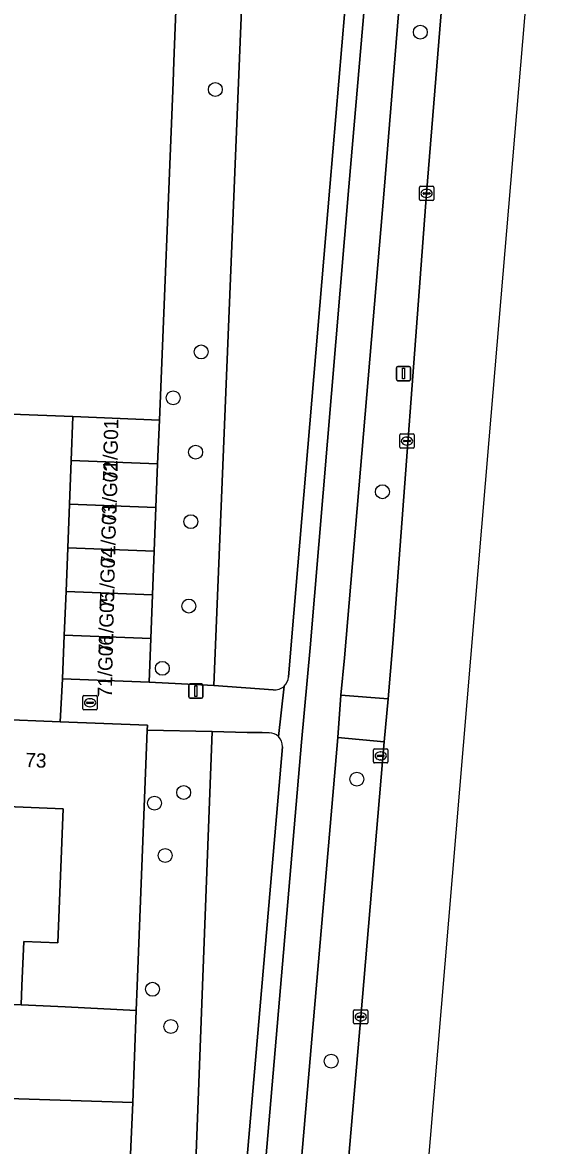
# Model space of a CAD drawing. Extents: x 160786 to 161429, y 386828 to 387485.
# Drawn here: x 161370.2 to 161407.6, y 386988.8 to 387067.7 of the extents above; entities that cross this region are included whole.
import ezdxf

# ---------------------------------------------------------------- set-up
doc = ezdxf.new("R2010")
doc.units = 0
for name, color, linetype in [('IMGEO_Berm_groen', 7, 'Continuous'), ('IMGEO_Boom', 7, 'Continuous'), ('IMGEO_Brandkraan', 7, 'Continuous'), ('IMGEO_Erf', 7, 'Continuous'), ('IMGEO_Fietspad_gesloten', 7, 'Continuous'), ('IMGEO_Groenvoorziening', 7, 'Continuous'), ('IMGEO_Kolk', 7, 'Continuous'), ('IMGEO_Lichtmast', 7, 'Continuous'), ('IMGEO_Pand', 7, 'Continuous'), ('IMGEO_Pand_nummerreeks', 7, 'Continuous'), ('IMGEO_Rijbaan_lokaal_gesloten', 7, 'Continuous'), ('IMGEO_Rijbaan_lokaal_open', 7, 'Continuous'), ('IMGEO_Voetpad_open', 7, 'Continuous')]:
    doc.layers.add(name, color=color, linetype=linetype)

msp = doc.modelspace()

# ---------------------------------------------------------------- linework, layer by layer
at = {"layer": 'IMGEO_Berm_groen'}
for points in [[(161399.932, 387071.853), (161396.957, 387072.068), (161395.639, 387055.923), (161392.853, 387023.047), (161392.609, 387020.441), (161395.92, 387020.164), (161396.257, 387024.055), (161398.628, 387055.685)], [(161395.645, 387017.152), (161392.377, 387017.448), (161386.443, 386948.447), (161389.725, 386948.174), (161390.641, 386959.132), (161392.331, 386978.524), (161393.997, 386997.829)]]:
    msp.add_lwpolyline(points, close=True, dxfattribs=at)
at = {"layer": 'IMGEO_Boom'}
for centre in [(161398.185, 387067.02), (161383.777, 387062.987), (161382.784, 387044.546), (161380.812, 387041.324), (161382.391, 387037.502), (161395.52, 387034.725), (161382.059, 387032.622), (161381.912, 387026.693), (161380.055, 387022.317), (161393.718, 387014.53), (161381.554, 387013.595), (161379.509, 387012.849), (161380.255, 387009.165), (161379.364, 386999.767), (161380.646, 386997.154), (161391.916, 386994.712)]:
    msp.add_circle(centre, 0.489, dxfattribs=at)
at = {"layer": 'IMGEO_Brandkraan'}
for p, q in [((161374.472, 387019.471), (161374.472, 387020.323)), ((161374.547, 387020.397), (161375.399, 387020.397)), ((161375.473, 387020.323), (161375.473, 387019.471)), ((161374.731, 387019.891), (161374.731, 387019.903)), ((161375.169, 387019.854), (161374.771, 387019.854)), ((161374.774, 387019.94), (161375.172, 387019.94)), ((161374.983, 387019.617), (161374.958, 387019.617)), ((161374.96, 387020.177), (161374.985, 387020.177)), ((161375.215, 387019.903), (161375.215, 387019.891)), ((161375.399, 387019.397), (161374.547, 387019.397))]:
    msp.add_line(p, q, dxfattribs=at)
for points in [[(161374.472, 387019.471), (161374.472, 387020.323)], [(161374.547, 387020.397), (161375.399, 387020.397)], [(161375.473, 387020.323), (161375.473, 387019.471)], [(161375.399, 387019.397), (161374.547, 387019.397)]]:
    msp.add_lwpolyline(points, dxfattribs=at)
for centre, radius, start, end in [((161374.549, 387020.321), 0.0765, 91.55205, 178.44795), ((161374.549, 387020.321), 0.0765, 91.55205, 178.44795), ((161375.397, 387020.321), 0.0765, 1.55205, 88.44795), ((161375.397, 387020.321), 0.0765, 1.55205, 88.44795), ((161374.771, 387019.9), 0.0403, 85.87752, 175.75265), ((161374.768, 387019.89), 0.0366, 178.93798, 274.71019), ((161375.172, 387019.897), 0.043, 264.86636, 352.45326), ((161375.176, 387019.902), 0.0386, 1.73085, 96.63898), ((161374.549, 387019.473), 0.0765, 181.55205, 268.44795), ((161374.549, 387019.473), 0.0765, 181.55205, 268.44795), ((161375.397, 387019.473), 0.0765, 271.55205, 358.44795), ((161375.397, 387019.473), 0.0765, 271.55205, 358.44795)]:
    msp.add_arc(centre, radius, start, end, dxfattribs=at)
for centre, major_axis, ratio, start_param, end_param in [((161374.959, 387019.897), (-0.387, 0.002), 0.722429, 4.712389, 7.853982), ((161374.984, 387019.897), (-0.39, 0.002), 0.717154, 1.570796, 4.712389)]:
    msp.add_ellipse(centre, major_axis=major_axis, ratio=ratio, start_param=start_param, end_param=end_param, dxfattribs=at)
at = {"layer": 'IMGEO_Erf'}
for points in [[(161380.817, 387063.5), (161380.873, 387064.957), (161381.079, 387070.343)], [(161332.397, 387034.68), (161332.673, 387041.57), (161373.771, 387039.999), (161379.846, 387039.759), (161380.817, 387063.5)], [(161377.988, 386991.819), (161324.809, 386993.526), (161324.595, 386988.451)], [(161329.654, 386962.268), (161329.879, 386969.558), (161370.877, 386967.928), (161370.886, 386968.153), (161376.903, 386967.918), (161377.988, 386991.819)]]:
    msp.add_lwpolyline(points, dxfattribs=at)
msp.add_lwpolyline([(161363.717, 387018.934), (161361.04, 387019.026), (161360.826, 387014.031), (161360.78, 387012.946), (161360.442, 387005.039), (161363.189, 387004.926), (161362.992, 387000), (161362.951, 386998.982), (161370.121, 386998.674), (161370.177, 387000), (161370.309, 387003.128), (161372.71, 387003.032), (161373.086, 387012.454), (161363.473, 387012.838), (161363.517, 387013.939)], close=True, dxfattribs=at)
at = {"layer": 'IMGEO_Fietspad_gesloten'}
for points in [[(161407.533, 387249.962), (161407.461, 387247.985), (161406.867, 387233.118), (161405.924, 387208.411), (161404.815, 387191.258), (161403.255, 387173.245), (161393.155, 387056.153), (161390.436, 387023.76), (161389.845, 387017.132), (161384.142, 386950.642), (161379.486, 386896.649), (161376.409, 386860.953), (161376.305, 386860.089), (161375.969, 386856.03)], [(161378.308, 386855.734), (161378.639, 386859.88), (161379.101, 386865.962), (161379.245, 386867.859), (161380.021, 386874.137), (161380.151, 386878.097), (161380.414, 386880.385), (161381.868, 386896.26), (161386.193, 386945.455), (161386.443, 386948.447), (161392.377, 387017.448), (161392.609, 387020.441), (161392.853, 387023.047), (161395.639, 387055.923), (161396.957, 387072.068), (161397.194, 387075.026), (161397.55, 387078.957), (161397.852, 387082.755), (161398.745, 387093.387), (161404.702, 387161.369), (161404.959, 387164.349), (161405.728, 387172.922), (161407.304, 387191.154)]]:
    msp.add_lwpolyline(points, dxfattribs=at)
at = {"layer": 'IMGEO_Groenvoorziening'}
for points in [[(161386.485, 387089.822), (161381.894, 387090.013), (161381.079, 387070.343), (161380.873, 387064.957), (161380.817, 387063.5), (161379.846, 387039.759), (161379.725, 387036.688), (161379.603, 387033.618), (161379.482, 387030.547), (161379.36, 387027.476), (161379.239, 387024.406), (161379.117, 387021.335), (161383.674, 387021.117)], [(161382.888, 387000), (161383.565, 387017.876), (161378.999, 387017.983), (161378.28, 387000), (161378.212, 386998.287), (161377.988, 386991.819), (161376.903, 386967.918), (161376.782, 386964.832), (161376.661, 386961.745), (161376.541, 386958.659), (161376.42, 386955.572), (161376.299, 386952.486), (161376.178, 386949.399), (161380.958, 386949.059), (161380.963, 386949.203)], [(161377.988, 386991.819), (161378.212, 386998.287), (161373.218, 386998.526), (161370.121, 386998.674), (161362.951, 386998.982), (161352.162, 386999.342), (161345.043, 386999.585), (161335.274, 387000), (161334.12, 387000.049), (161327.057, 387000.352), (161321.12, 387000.598), (161316.124, 387000.805), (161309.14, 387001.096), (161305.991, 387001.219), (161305.942, 387000), (161305.522, 386989.524), (161318.951, 386988.957), (161319.154, 386993.764), (161324.809, 386993.526)]]:
    msp.add_lwpolyline(points, close=True, dxfattribs=at)
for points in [[(161393.673, 387089.63), (161386.485, 387089.822), (161383.674, 387021.117), (161387.834, 387020.815)], [(161391.829, 387056.128), (161394.565, 387088.425)], [(161388.918, 387021.703), (161389.162, 387024.538), (161391.829, 387056.128)], [(161387.569, 387017.788), (161387.065, 387017.817), (161386.225, 387017.813), (161386.021, 387017.818), (161383.565, 387017.876), (161382.888, 387000), (161380.963, 386949.203), (161380.958, 386949.059), (161381.225, 386949.04), (161381.89, 386949.011)], [(161382.742, 386949.926), (161388.492, 387016.802)]]:
    msp.add_lwpolyline(points, dxfattribs=at)
for centre, radius, start, end in [((161387.956, 387021.776), 0.965, 313.41295, 355.66744), ((161387.952, 387021.775), 0.967, 263.02214, 313.62865), ((161387.571, 387016.863), 0.925, 45.70508, 90.11398), ((161387.573, 387016.866), 0.921, 355.99275, 45.65683)]:
    msp.add_arc(centre, radius, start, end, dxfattribs=at)
at = {"layer": 'IMGEO_Kolk'}
for p, q in [((161398.127, 387055.259), (161398.127, 387056.111)), ((161398.202, 387056.185), (161399.054, 387056.185)), ((161398.615, 387055.965), (161398.64, 387055.965)), ((161399.128, 387056.111), (161399.128, 387055.259)), ((161399.054, 387055.185), (161398.202, 387055.185)), ((161398.386, 387055.679), (161398.386, 387055.691)), ((161398.824, 387055.642), (161398.426, 387055.642)), ((161398.429, 387055.728), (161398.827, 387055.728)), ((161398.638, 387055.405), (161398.613, 387055.405)), ((161398.87, 387055.691), (161398.87, 387055.679)), ((161396.75, 387037.861), (161396.75, 387038.713)), ((161396.825, 387038.787), (161397.677, 387038.787)), ((161397.238, 387038.567), (161397.263, 387038.567)), ((161397.751, 387038.713), (161397.751, 387037.861)), ((161397.677, 387037.787), (161396.825, 387037.787)), ((161397.009, 387038.281), (161397.009, 387038.293)), ((161397.447, 387038.244), (161397.049, 387038.244)), ((161397.052, 387038.33), (161397.45, 387038.33)), ((161397.261, 387038.007), (161397.236, 387038.007)), ((161397.493, 387038.293), (161397.493, 387038.281)), ((161394.901, 387015.74), (161394.901, 387016.592)), ((161394.976, 387016.666), (161395.828, 387016.666)), ((161395.389, 387016.446), (161395.414, 387016.446)), ((161395.902, 387016.592), (161395.902, 387015.74)), ((161395.828, 387015.666), (161394.976, 387015.666)), ((161395.16, 387016.16), (161395.16, 387016.172)), ((161395.598, 387016.123), (161395.2, 387016.123)), ((161395.203, 387016.209), (161395.601, 387016.209)), ((161395.412, 387015.886), (161395.387, 387015.886)), ((161395.644, 387016.172), (161395.644, 387016.16)), ((161393.496, 386997.403), (161393.496, 386998.255)), ((161393.571, 386998.329), (161394.423, 386998.329)), ((161394.497, 386998.255), (161394.497, 386997.403)), ((161393.755, 386997.823), (161393.755, 386997.835)), ((161394.193, 386997.786), (161393.795, 386997.786)), ((161393.798, 386997.872), (161394.196, 386997.872)), ((161394.007, 386997.549), (161393.982, 386997.549)), ((161393.984, 386998.109), (161394.009, 386998.109)), ((161394.239, 386997.835), (161394.239, 386997.823)), ((161394.423, 386997.329), (161393.571, 386997.329))]:
    msp.add_line(p, q, dxfattribs=at)
for points in [[(161398.127, 387055.259), (161398.127, 387056.111)], [(161398.202, 387056.185), (161399.054, 387056.185)], [(161399.128, 387056.111), (161399.128, 387055.259)], [(161399.054, 387055.185), (161398.202, 387055.185)], [(161396.75, 387037.861), (161396.75, 387038.713)], [(161396.825, 387038.787), (161397.677, 387038.787)], [(161397.751, 387038.713), (161397.751, 387037.861)], [(161397.677, 387037.787), (161396.825, 387037.787)], [(161394.901, 387015.74), (161394.901, 387016.592)], [(161394.976, 387016.666), (161395.828, 387016.666)], [(161395.902, 387016.592), (161395.902, 387015.74)], [(161395.828, 387015.666), (161394.976, 387015.666)], [(161393.496, 386997.403), (161393.496, 386998.255)], [(161393.571, 386998.329), (161394.423, 386998.329)], [(161394.497, 386998.255), (161394.497, 386997.403)], [(161394.423, 386997.329), (161393.571, 386997.329)]]:
    msp.add_lwpolyline(points, dxfattribs=at)
for centre, radius, start, end in [((161398.204, 387056.109), 0.0765, 91.55205, 178.44795), ((161398.204, 387056.109), 0.0765, 91.55205, 178.44795), ((161399.052, 387056.109), 0.0765, 1.55205, 88.44795), ((161399.052, 387056.109), 0.0765, 1.55205, 88.44795), ((161398.204, 387055.261), 0.0765, 181.55205, 268.44795), ((161398.204, 387055.261), 0.0765, 181.55205, 268.44795), ((161398.426, 387055.688), 0.0403, 85.87752, 175.75265), ((161398.423, 387055.678), 0.0366, 178.93798, 274.71019), ((161398.827, 387055.685), 0.043, 264.86636, 352.45326), ((161398.831, 387055.69), 0.0386, 1.73085, 96.63898), ((161399.052, 387055.261), 0.0765, 271.55205, 358.44795), ((161399.052, 387055.261), 0.0765, 271.55205, 358.44795), ((161396.827, 387038.711), 0.0765, 91.55205, 178.44795), ((161396.827, 387038.711), 0.0765, 91.55205, 178.44795), ((161397.675, 387038.711), 0.0765, 1.55205, 88.44795), ((161397.675, 387038.711), 0.0765, 1.55205, 88.44795), ((161396.827, 387037.863), 0.0765, 181.55205, 268.44795), ((161396.827, 387037.863), 0.0765, 181.55205, 268.44795), ((161397.049, 387038.29), 0.0403, 85.87752, 175.75265), ((161397.046, 387038.28), 0.0366, 178.93798, 274.71019), ((161397.45, 387038.287), 0.043, 264.86636, 352.45326), ((161397.454, 387038.292), 0.0386, 1.73085, 96.63898), ((161397.675, 387037.863), 0.0765, 271.55205, 358.44795), ((161397.675, 387037.863), 0.0765, 271.55205, 358.44795), ((161394.978, 387016.59), 0.0765, 91.55205, 178.44795), ((161394.978, 387016.59), 0.0765, 91.55205, 178.44795), ((161395.826, 387016.59), 0.0765, 1.55205, 88.44795), ((161395.826, 387016.59), 0.0765, 1.55205, 88.44795), ((161394.978, 387015.742), 0.0765, 181.55205, 268.44795), ((161394.978, 387015.742), 0.0765, 181.55205, 268.44795), ((161395.2, 387016.169), 0.0403, 85.87752, 175.75265), ((161395.197, 387016.159), 0.0366, 178.93798, 274.71019), ((161395.601, 387016.166), 0.043, 264.86636, 352.45326), ((161395.605, 387016.171), 0.0386, 1.73085, 96.63898), ((161395.826, 387015.742), 0.0765, 271.55205, 358.44795), ((161395.826, 387015.742), 0.0765, 271.55205, 358.44795), ((161393.573, 386998.253), 0.0765, 91.55205, 178.44795), ((161393.573, 386998.253), 0.0765, 91.55205, 178.44795), ((161394.421, 386998.253), 0.0765, 1.55205, 88.44795), ((161394.421, 386998.253), 0.0765, 1.55205, 88.44795), ((161393.795, 386997.832), 0.0403, 85.87752, 175.75265), ((161393.792, 386997.822), 0.0366, 178.93798, 274.71019), ((161394.196, 386997.829), 0.043, 264.86636, 352.45326), ((161394.2, 386997.834), 0.0386, 1.73085, 96.63898), ((161393.573, 386997.405), 0.0765, 181.55205, 268.44795), ((161393.573, 386997.405), 0.0765, 181.55205, 268.44795), ((161394.421, 386997.405), 0.0765, 271.55205, 358.44795), ((161394.421, 386997.405), 0.0765, 271.55205, 358.44795)]:
    msp.add_arc(centre, radius, start, end, dxfattribs=at)
for centre, major_axis, ratio, start_param, end_param in [((161398.614, 387055.685), (-0.387, 0.002), 0.722429, 4.712389, 7.853982), ((161398.639, 387055.685), (-0.39, 0.002), 0.717154, 1.570796, 4.712389), ((161397.237, 387038.287), (-0.387, 0.002), 0.722429, 4.712389, 7.853982), ((161397.262, 387038.287), (-0.39, 0.002), 0.717154, 1.570796, 4.712389), ((161395.388, 387016.166), (-0.387, 0.002), 0.722429, 4.712389, 7.853982), ((161395.413, 387016.166), (-0.39, 0.002), 0.717154, 1.570796, 4.712389), ((161393.983, 386997.829), (-0.387, 0.002), 0.722429, 4.712389, 7.853982), ((161394.008, 386997.829), (-0.39, 0.002), 0.717154, 1.570796, 4.712389)]:
    msp.add_ellipse(centre, major_axis=major_axis, ratio=ratio, start_param=start_param, end_param=end_param, dxfattribs=at)
at = {"layer": 'IMGEO_Lichtmast'}
for p, q in [((161396.503, 387042.628), (161396.503, 387043.428)), ((161396.503, 387043.428), (161396.503, 387042.628)), ((161396.603, 387043.528), (161397.393, 387043.528)), ((161397.393, 387043.528), (161396.603, 387043.528)), ((161397.493, 387043.428), (161397.493, 387042.628)), ((161397.493, 387042.628), (161397.493, 387043.428)), ((161397.393, 387042.528), (161396.603, 387042.528)), ((161396.603, 387042.528), (161397.393, 387042.528)), ((161381.907, 387020.32), (161381.907, 387021.12)), ((161381.907, 387021.12), (161381.907, 387020.32)), ((161382.007, 387021.22), (161382.797, 387021.22)), ((161382.797, 387021.22), (161382.007, 387021.22)), ((161382.897, 387021.12), (161382.897, 387020.32)), ((161382.897, 387020.32), (161382.897, 387021.12)), ((161382.797, 387020.22), (161382.007, 387020.22)), ((161382.007, 387020.22), (161382.797, 387020.22))]:
    msp.add_line(p, q, dxfattribs=at)
for points in [[(161396.923, 387043.403), (161397.073, 387043.403), (161397.073, 387042.653), (161396.923, 387042.653), (161396.923, 387043.403)], [(161382.327, 387021.095), (161382.477, 387021.095), (161382.477, 387020.345), (161382.327, 387020.345), (161382.327, 387021.095)]]:
    msp.add_lwpolyline(points, dxfattribs=at)
for centre, start, end in [((161396.603, 387043.428), 90, 180), ((161396.603, 387043.428), 90, 180), ((161397.393, 387043.428), 0, 90), ((161397.393, 387043.428), 360, 90), ((161396.603, 387042.628), 180, 270), ((161396.603, 387042.628), 180, 270), ((161397.393, 387042.628), 270, 0), ((161397.393, 387042.628), 270, 0), ((161382.007, 387021.12), 90, 180), ((161382.007, 387021.12), 90, 180), ((161382.797, 387021.12), 0, 90), ((161382.797, 387021.12), 360, 90), ((161382.007, 387020.32), 180, 270), ((161382.007, 387020.32), 180, 270), ((161382.797, 387020.32), 270, 0), ((161382.797, 387020.32), 270, 0)]:
    msp.add_arc(centre, 0.1, start, end, dxfattribs=at)
at = {"layer": 'IMGEO_Pand'}
for points in [[(161373.65, 387036.929), (161379.725, 387036.688), (161379.846, 387039.759), (161373.771, 387039.999)], [(161373.528, 387033.858), (161379.603, 387033.618), (161379.725, 387036.688), (161373.65, 387036.929)], [(161373.407, 387030.787), (161379.482, 387030.547), (161379.603, 387033.618), (161373.528, 387033.858)], [(161373.285, 387027.717), (161379.36, 387027.476), (161379.482, 387030.547), (161373.407, 387030.787)], [(161373.164, 387024.646), (161379.239, 387024.406), (161379.36, 387027.476), (161373.285, 387027.717)], [(161379.117, 387021.335), (161379.239, 387024.406), (161373.164, 387024.646), (161373.042, 387021.575)], [(161378.999, 387017.983), (161379.013, 387018.323), (161372.867, 387018.569), (161363.717, 387018.934), (161363.517, 387013.939), (161363.473, 387012.838), (161373.086, 387012.454), (161372.71, 387003.032), (161370.309, 387003.128), (161370.177, 387000), (161370.121, 386998.674), (161373.218, 386998.526), (161378.212, 386998.287), (161378.28, 387000)]]:
    msp.add_lwpolyline(points, close=True, dxfattribs=at)
at = {"layer": 'IMGEO_Rijbaan_lokaal_gesloten'}
for points in [[(161376.562, 386828.305), (161385.332, 386827.741), (161389.859, 386881.623), (161403.029, 387038.37), (161407.62, 387092.708)], [(161399.932, 387071.853), (161398.628, 387055.685), (161396.257, 387024.055), (161395.92, 387020.164), (161395.645, 387017.152), (161393.997, 386997.829), (161392.331, 386978.524), (161390.641, 386959.132), (161389.725, 386948.174), (161389.46, 386945.188), (161387.076, 386917.62), (161385.411, 386898.291), (161383.44, 386875.95), (161383.252, 386873.773), (161382.445, 386867.469), (161382.202, 386865.584), (161381.409, 386859.417), (161381.119, 386856.234), (161378.165, 386837.436), (161377.278, 386832.285), (161376.562, 386828.305)]]:
    msp.add_lwpolyline(points, dxfattribs=at)
at = {"layer": 'IMGEO_Rijbaan_lokaal_open'}
for points in [[(161373.285, 387027.717), (161373.407, 387030.787), (161373.528, 387033.858), (161373.65, 387036.929), (161373.771, 387039.999), (161332.673, 387041.57), (161332.397, 387034.68)], [(161326.242, 387028.985), (161307.145, 387029.702), (161306.892, 387024.216), (161306.763, 387021.339), (161307.084, 387021.324), (161309.806, 387021.211), (161325.056, 387020.578), (161327.814, 387020.467), (161343.045, 387019.819), (161345.756, 387019.68), (161361.04, 387019.026), (161363.717, 387018.934), (161372.867, 387018.569), (161373.042, 387021.575), (161373.164, 387024.646), (161373.285, 387027.717)]]:
    msp.add_lwpolyline(points, dxfattribs=at)
at = {"layer": 'IMGEO_Voetpad_open'}
for points in [[(161375.969, 386856.03), (161376.305, 386860.089), (161376.409, 386860.953), (161379.486, 386896.649), (161384.142, 386950.642), (161389.845, 387017.132), (161390.436, 387023.76), (161393.155, 387056.153), (161403.255, 387173.245), (161404.815, 387191.258), (161405.924, 387208.411), (161406.867, 387233.118), (161407.461, 387247.985), (161407.533, 387249.962)], [(161394.565, 387088.425), (161391.829, 387056.128), (161389.162, 387024.538), (161388.918, 387021.703)], [(161387.834, 387020.815), (161383.674, 387021.117), (161379.117, 387021.335), (161373.042, 387021.575), (161372.867, 387018.569), (161379.013, 387018.323), (161378.999, 387017.983), (161383.565, 387017.876), (161386.021, 387017.818), (161386.225, 387017.813), (161387.065, 387017.817), (161387.569, 387017.788)], [(161388.619, 387021.075), (161388.217, 387017.525)], [(161388.217, 387017.525), (161388.619, 387021.075)], [(161388.492, 387016.802), (161382.742, 386949.926)]]:
    msp.add_lwpolyline(points, dxfattribs=at)
msp.add_lwpolyline([(161395.92, 387020.164), (161392.609, 387020.441), (161392.377, 387017.448), (161395.645, 387017.152)], close=True, dxfattribs=at)
for centre, radius, start, end in [((161387.956, 387021.776), 0.965, 313.41295, 355.66744), ((161387.952, 387021.775), 0.967, 263.02214, 313.62865), ((161387.571, 387016.863), 0.925, 45.70508, 90.11398), ((161387.573, 387016.866), 0.921, 355.99275, 45.65683)]:
    msp.add_arc(centre, radius, start, end, dxfattribs=at)

# ---------------------------------------------------------------- texts
at = {"layer": 'IMGEO_Pand_nummerreeks'}
for s, rotation, p in [('71/G01', 88.70226, (161376.868, 387035.464)), ('71/G02', 88.70226, (161376.824, 387032.477)), ('71/G03', 88.70226, (161376.72, 387029.478)), ('71/G04', 88.70226, (161376.647, 387026.436)), ('71/G05', 88.70226, (161376.574, 387023.303)), ('71/G06', 88.70226, (161376.501, 387020.258)), ('73', 357.7139, (161370.407, 387015.385))]:
    msp.add_text(s, height=1, rotation=rotation, dxfattribs=at).set_placement(p)

doc.saveas('drawing.dxf')
